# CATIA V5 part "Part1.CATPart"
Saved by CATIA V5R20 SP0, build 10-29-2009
Part number: Part1
Bounding box of the stored display mesh (mm): x -20 to 20, y -20.95 to 932.78, z -45.2 to 45.2
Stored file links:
  E:\Ehsan\Amoozesh\CATIA\CATIA Course\Basic\Exercises\Assembly\6\Part1.CATPart
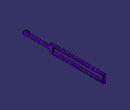
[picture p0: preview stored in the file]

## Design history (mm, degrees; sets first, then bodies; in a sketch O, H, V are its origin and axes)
Body1 (main body)
  Sketch1 on yz-plane, origin (0, 0, 0), H (0, 1, 0), V (0, 0, 1)
    construction line L1 (0, 0) -> (328.73, 0)
    line L2 (17.8051, 11.04) -> (281.82, 11.04)
    arc A1 centre (0, 0) radius 20.95 from (17.8051, -11.04) to (17.8051, 11.04) cw
    line L3 (295.86, 45.2) -> (932.78, 45.2)
    line L4 (932.78, 45.2) -> (932.78, -45.2)
    line L5 (932.78, -45.2) -> (295.86, -45.2)
    line L6 (295.86, -45.2) -> (295.86, -25.08)
    line L7 (326, 27.39) -> (919.1, 27.39)
    line L8 (919.1, 27.39) -> (919.1, -27.39)
    line L9 (919.1, -27.39) -> (326, -27.39)
    line L10 (326, -27.39) -> (326, -11.04)
    circle A2 centre (0, 0) radius 11.04
    line L11 (326, 0) -> (326, 27.39)
    line L12 (326, -11.04) -> (326, 0)
    line L13 (295.86, 25.08) -> (295.86, 45.2)
    line L14 (281.82, -11.04) -> (17.8051, -11.04)
    arc A3 centre (281.82, 25.08) radius 14.04 from (281.82, 11.04) to (295.86, 25.08) ccw
    arc A4 centre (281.82, -25.08) radius 14.04 from (281.82, -11.04) to (295.86, -25.08) cw
  MultiPad1: profile Sketch1, domains (length 0; length 20; length 20 / length 20)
